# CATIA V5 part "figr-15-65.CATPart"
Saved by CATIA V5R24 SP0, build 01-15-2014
Part number: Part1
Bounding box of the stored display mesh (mm): x -92.936 to 49.742, y -31.904 to 31.904, z 0 to 63.808
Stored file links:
  D:\KAVITA\CATIA V5-6R2014 Project_ Kavita\CATIA V5-6R2014_partfiles\Partfiles\c15_catia_v5-6r2014_prt\figr-15-65.CATPart
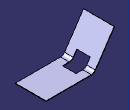
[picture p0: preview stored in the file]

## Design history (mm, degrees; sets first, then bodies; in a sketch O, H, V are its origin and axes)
SheetMetalParameters1: Thickness 1, BendRadius 10, KFactor 0.5 {= log(min(100,max(20*SheetMetalParameters1.BendRadius,SheetMetalParameters1.Thickness)/SheetMetalParameters1.Thickness))/log(100)/2}, ReliefRadialLength 1, ReliefAxialLength 2, MinimumBendRadius 0
Body1 (main body)
  Sketch1 on xy-plane, origin (0, 0, 0), H (1, 0, 0), V (0, 1, 0)
    line L1 (49.7419, 31.9042) -> (49.7419, -31.9042)
    line L2 (49.7419, -31.9042) -> (-49.7419, -31.9042)
    line L3 (-49.7419, -31.9042) -> (-49.7419, 31.9042)
    line L4 (-49.7419, 31.9042) -> (49.7419, 31.9042)
    vertical: L1 V, L3 V
    horizontal: L2 H, L4 H
    equidistance: L1 L3 O, L2 L4 O
  Wall1: Thickness 1, Profile Sketch1
  d_NewWallOnEdge1: NewWallOnEdge_Edge edge [face of Wall1 | face of Wall1], NewWallOnEdge_Length 63.8083, NewWallOnEdge_HeightLimitOffset 0, NewWallOnEdge_WidthOffset1 0, NewWallOnEdge_WidthOffset2 0, NewWallOnEdge_Angle 124, NewWallOnEdge_BendRadiusValue 10 {= SheetMetalParameters1.BendRadius}, NewWallOnEdge_BendTable SheetMetalParameters1, KFacteur 0.5 {= log(min(100,max(20*d_NewWallOnEdge1.Radius,SheetMetalParameters1.Thickness)/SheetMetalParameters1.Thickness))/log(100)/2}
  Sketch2 on face of d_NewWallOnEdge1, origin (0, 0, 1), H (1, 0, 0), V (0, 1, 0)
    point P1 (-49.1841, 0)
    line L1 (-30.5497, 14.1437) -> (-30.5497, -14.1437)
    line L2 (-30.5497, -14.1437) -> (-67.8185, -14.1437)
    line L3 (-67.8185, -14.1437) -> (-67.8185, 14.1437)
    line L4 (-67.8185, 14.1437) -> (-30.5497, 14.1437)
    coincidence: P1 H
    vertical: L1 V, L3 V
    horizontal: L2 H, L4 H
    equidistance: L1 L3 P1, L2 L4 P1
  CutOut1: Direction Sketch2, EndLimit through (limit type 2), Orientation true, Profile Sketch2, StartLimit through (limit type 2)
